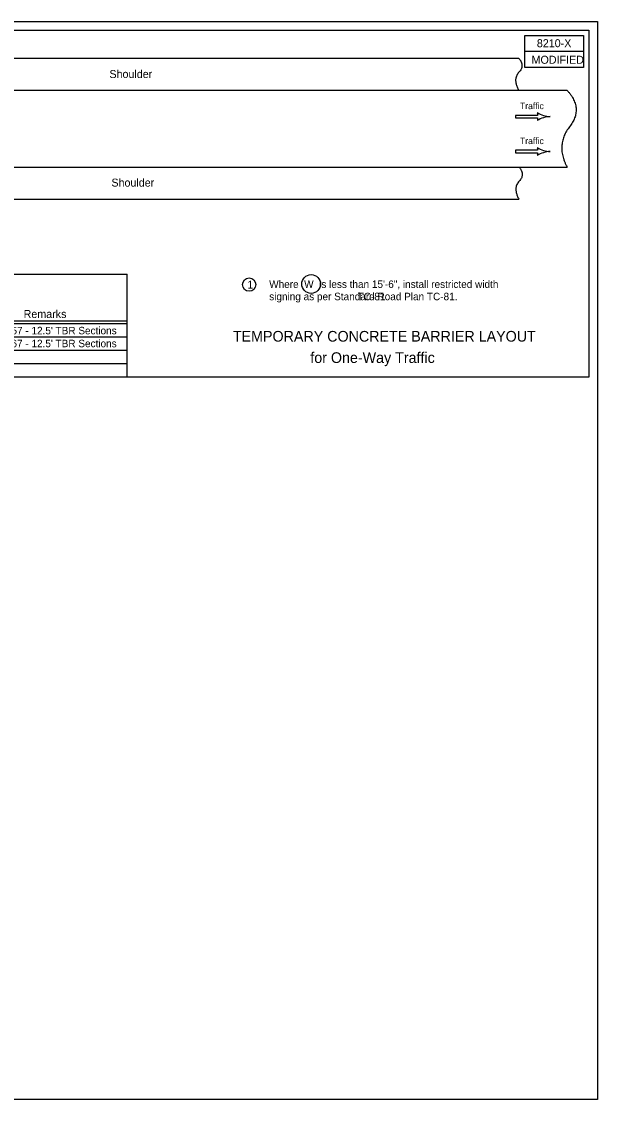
# Model space of a CAD drawing. Extents: x 5601 to 45668, y 7924 to 13839.
# Drawn here: x 12188 to 13268, y 7924 to 9944 of the extents above; entities that cross this region are included whole.
import ezdxf

# ---------------------------------------------------------------- set-up
doc = ezdxf.new("R2010")
doc.units = 0
for name, color, linetype in [('DisCLMLORPoints', 7, 'Continuous'), ('dsnAlignment', 7, 'Continuous'), ('dsnAlignmentCurveData', 7, 'Continuous'), ('dsnAlignmentStation', 7, 'Continuous'), ('dsnStdNameDate', 7, 'Continuous'), ('Level 1', 7, 'Continuous'), ('Level 12', 7, 'Continuous'), ('Level 4', 7, 'Continuous'), ('Level 63', 7, 'Continuous'), ('Shape', 7, 'Continuous'), ('SheetBorder', 7, 'Continuous')]:
    doc.layers.add(name, color=color, linetype=linetype)

msp = doc.modelspace()

# ---------------------------------------------------------------- linework, layer by layer
at = {"layer": 'DisCLMLORPoints'}
for p, q in [((11135.2, 9352.9), (12386.4, 9352.9)), ((11135.2, 9327.9), (12386.4, 9327.9)), ((11135.2, 9302.9), (12386.4, 9302.9))]:
    msp.add_line(p, q, dxfattribs=at)
at = {"layer": 'dsnAlignment'}
for p, q in [((10146.6, 9927.9), (13251.6, 9927.9)), ((13251.6, 9927.9), (13251.6, 9277.9))]:
    msp.add_line(p, q, dxfattribs=at)
at = {"layer": 'dsnAlignmentStation'}
msp.add_line((13251.6, 9277.9), (10146.6, 9277.9), dxfattribs=at)
at = {"layer": 'Level 1'}
for p, q in [((11771.8, 9875.3), (13120.2, 9875.3)), ((11879.3, 9815.3), (13210.6, 9815.3)), ((13154.9, 9768.1), (13113.7, 9768.1)), ((13113.7, 9768.1), (13113.7, 9763.6)), ((13113.7, 9763.6), (13154.9, 9763.6)), ((13154.9, 9773.4), (13154.9, 9768.1)), ((13154.9, 9763.6), (13154.9, 9758.4)), ((13178.8, 9765.9), (13178.8, 9765.9)), ((13154.9, 9702.7), (13113.7, 9702.7)), ((13113.7, 9702.7), (13113.7, 9698.2)), ((13113.7, 9698.2), (13154.9, 9698.2)), ((13154.9, 9707.9), (13154.9, 9702.7)), ((13154.9, 9698.2), (13154.9, 9692.9)), ((13178.8, 9700.4), (13178.8, 9700.4)), ((11741.8, 9671.3), (13210.6, 9671.3)), ((11771.8, 9611.3), (13120.2, 9611.3)), ((11135.2, 9382.9), (12386.4, 9382.9)), ((11135.2, 9377.9), (12386.4, 9377.9))]:
    msp.add_line(p, q, dxfattribs=at)
for centre, radius in [((12614.9, 9451), 12.5), ((12731, 9452.2), 17.6)]:
    msp.add_circle(centre, radius, dxfattribs=at)
for centre, start, end in [((13180.8, 9814.2), 237.618, 267.648), ((13180.8, 9717.6), 92.352, 122.382), ((13180.8, 9748.7), 237.618, 267.648), ((13180.8, 9652.1), 92.352, 122.382)]:
    msp.add_arc(centre, 48.4, start, end, dxfattribs=at)
for points in [[(13120.2, 9875.3), (13132, 9861.2), (13108.4, 9836.2), (13119.8, 9815.3)], [(13210.6, 9815.3), (13242, 9780.9), (13188.6, 9712.8), (13210.6, 9671.3)], [(13120.7, 9671.3), (13132.5, 9657.1), (13108.9, 9632.1), (13120.2, 9611.3)]]:
    msp.add_open_spline(points, degree=2, dxfattribs=at)
at = {"layer": 'Level 4'}
msp.add_lwpolyline([(13241.6, 9917.9), (13241.6, 9857.9), (13131.6, 9857.9), (13131.6, 9917.9), (13241.6, 9917.9), (13241.6, 9887.9), (13131.6, 9887.9)], dxfattribs=at)
at = {"layer": 'Level 63'}
for p in [(11135.2, 9470.9), (12386.4, 9277.9)]:
    msp.add_line(p, (12386.4, 9470.9), dxfattribs=at)
at = {"layer": 'SheetBorder'}
msp.add_lwpolyline([(10132.5, 9944), (13267.5, 9944), (13267.5, 7924), (10132.5, 7924)], close=True, dxfattribs=at)

# ---------------------------------------------------------------- texts
at = {"layer": 'dsnAlignmentCurveData'}
for s, p in [("Stage 1:  57 - 12.5' TBR Sections", (12089.3, 9357.9)), ("Stage 2:  67 - 12.5' TBR Sections", (12089.3, 9333.7))]:
    msp.add_text(s, height=14, dxfattribs=at).set_placement(p)
at = {"layer": 'dsnStdNameDate'}
for s, p in [('8210-X', (13154, 9895.9)), ('MODIFIED', (13144.1, 9864.9))]:
    msp.add_text(s, height=15, dxfattribs=at).set_placement(p)
at = {"layer": 'Level 12'}
for s, height, p in [('Shoulder', 15, (12353, 9838.2)), ('Traffic', 12, (13122.4, 9779.9)), ('Traffic', 12, (13122.4, 9714.4)), ('Shoulder', 15, (12356.7, 9634.7)), ('1', 15, (12611.5, 9443.5)), ('Where  W  is less than 15\'-6", install restricted width', 14, (12652.4, 9444.8)), ('signing as per Standard Road Plan TC-81.', 14, (12652.4, 9421.8)), ('                                TC-81', 14, (12651.7, 9421.8)), ('Remarks', 15, (12192.2, 9388.5))]:
    msp.add_text(s, height=height, dxfattribs=at).set_placement(p)
at = {"layer": 'Shape'}
for s, p in [('TEMPORARY CONCRETE BARRIER LAYOUT', (12584.3, 9344.2)), ('for One-Way Traffic', (12729.4, 9304.2))]:
    msp.add_text(s, height=20, dxfattribs=at).set_placement(p)

doc.saveas('drawing.dxf')
